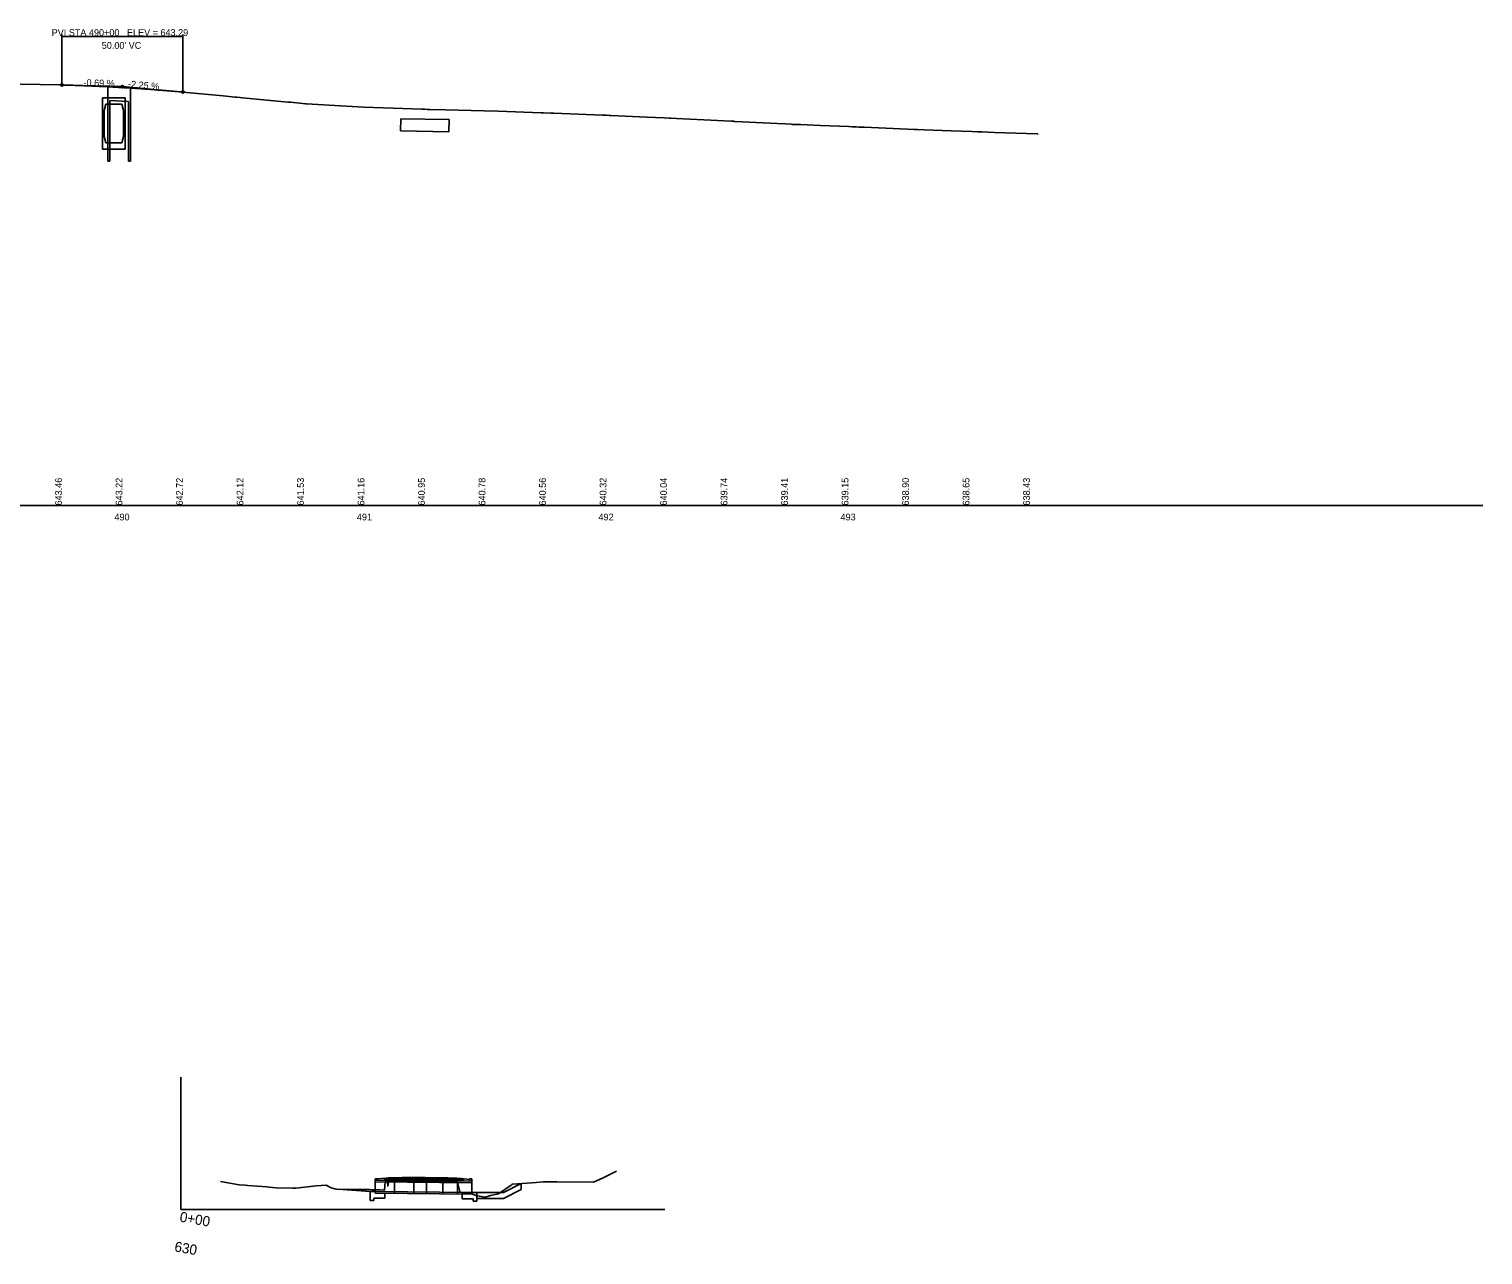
# Model space of a CAD drawing. Extents: x 2034057 to 2035954, y 247386 to 249135.
# Drawn here: x 2035353 to 2035954, y 248025 to 248532 of the extents above; entities that cross this region are included whole.
import ezdxf

# ---------------------------------------------------------------- set-up
doc = ezdxf.new("R2010")
doc.units = 0
for name, color, linetype in [('BR_X_SV_Deck_Top', 7, 'Continuous'), ('DR_X_Erosion_Control', 7, 'Continuous'), ('HY_X_Water_Edge', 7, 'Continuous'), ('PV_X_COP', 7, 'Continuous'), ('PV_X_EOP', 7, 'Continuous'), ('RD_X_Text', 7, 'Continuous'), ('SC_Scratch1', 7, 'Continuous'), ('SV_X_Toe_of_Slope', 7, 'Continuous'), ('SV_X_Top_of_Bank', 7, 'Continuous'), ('UT_X_Telecom', 7, 'Continuous'), ('VG_X_Shrub_Line_Lt', 7, 'Continuous')]:
    doc.layers.add(name, color=color, linetype=linetype)

msp = doc.modelspace()

# ---------------------------------------------------------------- linework, layer by layer
at = {"layer": 'BR_X_SV_Deck_Top'}
msp.add_open_spline([(2035366.81, 248508.9), (2035391.81, 248508.21), (2035416.81, 248505.96)], degree=2, dxfattribs=at)
at = {"layer": 'DR_X_Erosion_Control'}
for p, q in [((2035366.81, 248509.4), (2035366.81, 248529.77)), ((2035366.81, 248528.97), (2035416.81, 248528.97)), ((2035416.81, 248506.46), (2035416.81, 248529.77)), ((2035375.06, 248508.67), (2035391.81, 248508.21)), ((2035391.81, 248508.21), (2035407.85, 248506.77))]:
    msp.add_line(p, q, dxfattribs=at)
for centre in [(2035366.81, 248508.9), (2035391.81, 248508.21), (2035416.81, 248505.96)]:
    msp.add_circle(centre, 0.5, dxfattribs=at)
at = {"layer": 'HY_X_Water_Edge'}
for p, q in [((2035549.23, 248051.07), (2035556.57, 248054.74)), ((2035556.57, 248054.74), (2035556.57, 248052.24)), ((2035538.23, 248051.07), (2035549.23, 248051.07)), ((2035538.23, 248048.57), (2035549.23, 248048.57)), ((2035549.23, 248048.57), (2035556.57, 248052.24))]:
    msp.add_line(p, q, dxfattribs=at)
at = {"layer": 'PV_X_COP'}
for p, q in [((2035500.75, 248056.99), (2035497.23, 248056.64)), ((2035504.81, 248056.4), (2035499.75, 248056.2)), ((2035499.75, 248056.1), (2035499.75, 248056.2)), ((2035504.81, 248056.9), (2035500.25, 248056.72)), ((2035500.25, 248056.22), (2035500.25, 248056.72)), ((2035504.81, 248057.15), (2035500.75, 248056.99)), ((2035500.75, 248056.74), (2035500.75, 248056.99)), ((2035504.81, 248057.15), (2035515.98, 248057.24)), ((2035504.81, 248056.9), (2035515.98, 248056.99)), ((2035504.81, 248056.4), (2035515.98, 248056.49)), ((2035515.98, 248057.24), (2035527.15, 248056.99)), ((2035515.98, 248056.99), (2035527.15, 248056.74)), ((2035515.98, 248056.49), (2035527.15, 248056.24)), ((2035517.73, 248055.92), (2035517.73, 248056.45)), ((2035518.24, 248056.44), (2035518.24, 248056.94)), ((2035518.75, 248056.93), (2035518.75, 248057.18)), ((2035527.15, 248056.99), (2035531.97, 248056.79)), ((2035527.15, 248056.74), (2035532.47, 248056.52)), ((2035527.15, 248056.24), (2035532.97, 248056)), ((2035531.97, 248056.79), (2035531.97, 248056.54)), ((2035532.47, 248056.52), (2035532.47, 248056.02)), ((2035532.97, 248056), (2035532.97, 248055.77))]:
    msp.add_line(p, q, dxfattribs=at)
at = {"layer": 'PV_X_EOP'}
for p, q in [((2035494.23, 248051.47), (2035480.98, 248052.4)), ((2035531.97, 248056.79), (2035535.23, 248056.46))]:
    msp.add_line(p, q, dxfattribs=at)
at = {"layer": 'RD_X_Text'}
for p, q in [((2035506.85, 248494.97), (2035506.75, 248489.97)), ((2035506.85, 248494.97), (2035526.82, 248494.57)), ((2035526.82, 248494.57), (2035526.72, 248489.57)), ((2035506.75, 248489.97), (2035526.72, 248489.57))]:
    msp.add_line(p, q, dxfattribs=at)
at = {"layer": 'SC_Scratch1'}
for points in [[(2035341.74, 248509.37), (2035365.98, 248508.92), (2035366.55, 248508.91), (2035366.55, 248508.91), (2035390.84, 248507.98), (2035391.55, 248507.95), (2035415.32, 248506.1), (2035415.49, 248506.09), (2035416.74, 248505.97), (2035433.5, 248504.35), (2035438.46, 248503.87), (2035439.13, 248503.8), (2035440.41, 248503.67), (2035440.48, 248503.67), (2035441.37, 248503.58), (2035441.49, 248503.57), (2035454.36, 248502.37), (2035460.19, 248501.83), (2035461.23, 248501.73), (2035466.36, 248501.23), (2035466.37, 248501.23), (2035467.53, 248501.12), (2035467.86, 248501.1), (2035481.91, 248500.31), (2035491.58, 248499.72), (2035491.58, 248499.72), (2035503.63, 248499.33), (2035515.49, 248498.91), (2035516.57, 248498.87), (2035517.68, 248498.83), (2035518.8, 248498.8), (2035525.35, 248498.65), (2035541.29, 248498.21), (2035547.07, 248498.02), (2035564.81, 248497.38), (2035565.83, 248497.34), (2035565.84, 248497.34), (2035568.79, 248497.27), (2035570.01, 248497.23), (2035570.13, 248497.23), (2035590.14, 248496.44), (2035590.51, 248496.42), (2035591.89, 248496.36), (2035592.97, 248496.32), (2035592.98, 248496.31), (2035593.66, 248496.29), (2035608.48, 248495.63), (2035615.66, 248495.3), (2035617.88, 248495.19), (2035617.98, 248495.19), (2035618.37, 248495.17), (2035618.49, 248495.16), (2035620.8, 248495.05), (2035626.44, 248494.78), (2035643.31, 248493.94), (2035643.37, 248493.93), (2035643.37, 248493.93), (2035644.4, 248493.88), (2035644.67, 248493.87), (2035647.9, 248493.7), (2035662.36, 248492.96), (2035665.78, 248492.78), (2035668.25, 248492.64), (2035668.38, 248492.63), (2035668.38, 248492.63), (2035671.98, 248492.5), (2035680.32, 248492.16), (2035691.95, 248491.68), (2035693.34, 248491.62), (2035693.38, 248491.62), (2035694.9, 248491.55), (2035694.98, 248491.55), (2035696.1, 248491.51), (2035698.28, 248491.42), (2035716.25, 248490.68), (2035718.95, 248490.56), (2035719.9, 248490.52), (2035720.22, 248490.51), (2035720.3, 248490.5), (2035723.06, 248490.4), (2035734.21, 248489.96), (2035742.8, 248489.62), (2035745.16, 248489.52), (2035746.89, 248489.47), (2035752.17, 248489.28), (2035769.85, 248488.67), (2035770.13, 248488.66), (2035770.13, 248488.66)], [(2035432.3, 248055.54), (2035440.12, 248054.24), (2035442.54, 248054.02), (2035443.61, 248053.98), (2035451.61, 248053.39), (2035452.3, 248053.25), (2035455.32, 248053), (2035462.29, 248052.78), (2035463.15, 248052.82), (2035463.42, 248052.83), (2035471.86, 248053.81), (2035475.95, 248054.03), (2035478.02, 248052.98), (2035480.15, 248052.43), (2035484.94, 248052.28), (2035490.74, 248052.27), (2035493.94, 248052.27), (2035495.05, 248052.16), (2035498.33, 248052.09), (2035500.05, 248051.97), (2035500.28, 248053.86), (2035500.37, 248055.42), (2035500.7, 248055.42), (2035501.19, 248055.42), (2035501.38, 248055.52), (2035501.47, 248053.72), (2035501.74, 248055.21), (2035501.8, 248055.77), (2035502.44, 248055.98), (2035503.72, 248056.67), (2035504.7, 248056.93), (2035505.85, 248057.15), (2035507.43, 248057.18), (2035515.7, 248057.26), (2035516.98, 248057.24), (2035526.16, 248057.06), (2035526.49, 248056.99), (2035527.22, 248056.9), (2035529.95, 248056.48), (2035531.26, 248051.5), (2035531.32, 248051.17), (2035531.42, 248051.2), (2035531.44, 248051.19), (2035532, 248051.07), (2035535.22, 248050.74), (2035538.34, 248049.67), (2035541.76, 248049.17), (2035543.85, 248049.74), (2035547.23, 248050.55), (2035552.42, 248054.12), (2035552.68, 248054.32), (2035552.95, 248054.49), (2035553.08, 248054.48), (2035562.72, 248055.2), (2035565.61, 248055.4), (2035571.26, 248055.41), (2035586.41, 248055.31), (2035590.46, 248057.09), (2035595.97, 248059.93)]]:
    msp.add_lwpolyline(points, dxfattribs=at)
at = {"layer": 'SV_X_Toe_of_Slope'}
msp.add_line((2034991.81, 248335.07), (2035953.99, 248335.07), dxfattribs=at)
at = {"layer": 'SV_X_Top_of_Bank'}
for p, q in [((2035383.64, 248503.65), (2035383.64, 248482.32)), ((2035383.64, 248503.65), (2035392.98, 248503.65)), ((2035392.98, 248503.65), (2035392.98, 248482.32)), ((2035384.31, 248498.32), (2035384.98, 248500.99)), ((2035384.31, 248498.32), (2035384.31, 248487.65)), ((2035384.98, 248500.99), (2035391.64, 248500.99)), ((2035392.31, 248498.32), (2035391.64, 248500.99)), ((2035392.31, 248498.32), (2035392.31, 248487.65)), ((2035384.31, 248487.65), (2035384.98, 248484.99)), ((2035384.98, 248484.99), (2035391.64, 248484.99)), ((2035391.64, 248484.99), (2035392.31, 248487.65)), ((2035383.64, 248482.32), (2035392.98, 248482.32)), ((2035415.98, 248044), (2035415.98, 248098.74)), ((2035496.23, 248056.14), (2035496.23, 248056.64)), ((2035496.23, 248056.64), (2035497.23, 248056.64)), ((2035496.23, 248050.81), (2035496.23, 248056.14)), ((2035496.23, 248056.14), (2035536.23, 248055.74)), ((2035496.23, 248055.47), (2035536.23, 248055.07)), ((2035497.23, 248056.12), (2035497.23, 248056.64)), ((2035504.23, 248050.73), (2035504.23, 248056.06)), ((2035512.23, 248050.65), (2035512.23, 248055.98)), ((2035517.48, 248050.59), (2035517.48, 248055.93)), ((2035524.23, 248050.53), (2035524.23, 248055.86)), ((2035530.23, 248050.47), (2035530.23, 248055.8)), ((2035536.23, 248056.74), (2035535.23, 248056.74)), ((2035535.23, 248055.75), (2035535.23, 248056.74)), ((2035536.23, 248055.74), (2035536.23, 248056.74)), ((2035536.23, 248050.41), (2035536.23, 248055.74)), ((2035494.23, 248047.73), (2035494.23, 248051.47)), ((2035496.23, 248051.47), (2035494.23, 248051.47)), ((2035495.73, 248047.73), (2035494.23, 248047.73)), ((2035500.23, 248048.73), (2035495.73, 248048.73)), ((2035495.73, 248047.73), (2035495.73, 248048.73)), ((2035496.23, 248051.47), (2035536.23, 248051.07)), ((2035496.23, 248050.81), (2035536.23, 248050.41)), ((2035500.23, 248048.73), (2035500.23, 248050.73)), ((2035532.23, 248048.49), (2035532.23, 248050.49)), ((2035532.23, 248048.49), (2035536.73, 248048.49)), ((2035536.23, 248051.07), (2035538.23, 248051.07)), ((2035536.73, 248047.49), (2035536.73, 248048.49)), ((2035536.73, 248047.49), (2035538.23, 248047.49)), ((2035538.23, 248047.49), (2035538.23, 248051.07)), ((2035415.98, 248044), (2035615.98, 248044))]:
    msp.add_line(p, q, dxfattribs=at)
at = {"layer": 'UT_X_Telecom'}
for p, q in [((2035385.83, 248477.35), (2035385.83, 248508.17)), ((2035395.13, 248477.35), (2035395.13, 248507.67)), ((2035386.68, 248477.35), (2035386.68, 248502.47)), ((2035386.68, 248502.47), (2035394.28, 248502.07)), ((2035394.28, 248477.35), (2035394.28, 248502.07)), ((2035385.83, 248477.35), (2035386.68, 248477.35)), ((2035394.28, 248477.35), (2035395.13, 248477.35))]:
    msp.add_line(p, q, dxfattribs=at)
at = {"layer": 'VG_X_Shrub_Line_Lt'}
for p, q in [((2035515.7, 248057.26), (2035501.8, 248057.11)), ((2035501.8, 248057.11), (2035501.8, 248055.69)), ((2035501.8, 248055.69), (2035529.95, 248055.57)), ((2035515.7, 248057.26), (2035529.95, 248056.98)), ((2035529.95, 248056.98), (2035529.95, 248055.57))]:
    msp.add_line(p, q, dxfattribs=at)

# ---------------------------------------------------------------- texts
at = {"layer": 'DR_X_Erosion_Control'}
for s, p in [('PVI STA 490+00   ELEV = 643.29', (2035362.58, 248529.17)), ("50.00' VC", (2035383.27, 248523.86)), ('490', (2035388.53, 248328.89)), ('491', (2035488.7, 248328.89)), ('492', (2035588.54, 248328.89)), ('493', (2035688.55, 248328.89))]:
    msp.add_text(s, height=2.8, dxfattribs=at).set_placement(p)
for s, rotation, p in [('-0.69 %', 358.42221, (2035375.71, 248508.51)), ('-2.25 %', 354.85724, (2035394.02, 248508)), ('643.46', 90, (2035366.81, 248335.07)), ('643.22', 90, (2035391.81, 248335.07)), ('642.72', 90, (2035416.81, 248335.07)), ('642.12', 90, (2035441.81, 248335.07)), ('641.53', 90, (2035466.81, 248335.07)), ('641.16', 90, (2035491.81, 248335.07)), ('640.95', 90, (2035516.81, 248335.07)), ('640.78', 90, (2035541.81, 248335.07)), ('640.56', 90, (2035566.81, 248335.07)), ('640.32', 90, (2035591.81, 248335.07)), ('640.04', 90, (2035616.81, 248335.07)), ('639.74', 90, (2035641.81, 248335.07)), ('639.41', 90, (2035666.81, 248335.07)), ('639.15', 90, (2035691.81, 248335.07)), ('638.90', 90, (2035716.81, 248335.07)), ('638.65', 90, (2035741.81, 248335.07)), ('638.43', 90, (2035766.81, 248335.07))]:
    msp.add_text(s, height=2.8, rotation=rotation, dxfattribs=at).set_placement(p)
at = {"layer": 'SV_X_Top_of_Bank'}
for s, p in [('0+00', (2035415.26, 248039.06)), ('630', (2035413.09, 248026.75))]:
    msp.add_text(s, height=4.167, rotation=350, dxfattribs=at).set_placement(p)

doc.saveas('drawing.dxf')
